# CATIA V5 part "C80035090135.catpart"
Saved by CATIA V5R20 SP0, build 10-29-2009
Part number: C80035090135
Source: Unknown
Property "A": "90"
Property "ARTICLENO": "C80035090135"
Property "B": "45"
Property "BOMINFO": "C80035090135"
Property "C": "130"
Property "CA": "C80035090135"
Property "D1": "170"
Property "DES": "ROTATING EYEBOLT WITH RING Ton 35 M90x135"
Property "E": "165"
Property "H": "338"
Property "L": "135"
Property "LINA": "C80035090135"
Property "NB": "C80035090135"
Property "NBSYN": "$CODE."
Property "NN": "C800"
Property "NT": "Rotating eyebolt with ring"
Property "SIZE": "M90"
Property "SUPPLIER": "CF"
Property "SW": "134"
Property "WEIGHT": "29000"
Property "WLL": "35.00"
Bounding box of the stored display mesh (mm): x -90 to 90, y -135 to 383, z -85 to 85
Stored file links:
  C:\Users\Utente\Desktop\3D files 800\C80035090135.catpart
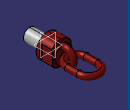
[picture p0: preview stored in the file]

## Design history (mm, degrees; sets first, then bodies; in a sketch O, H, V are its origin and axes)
Body1 "Geometry.1" (main body)
  Solid1 "C80035090135.catpart": solid without history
